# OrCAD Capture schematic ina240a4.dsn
size A; title: INA293 40-V High-Voltage, High Bandwidth, Unidirectional, 110-V Common-Mode Current-Sense Amplifier; rev: A; note: SBOS870
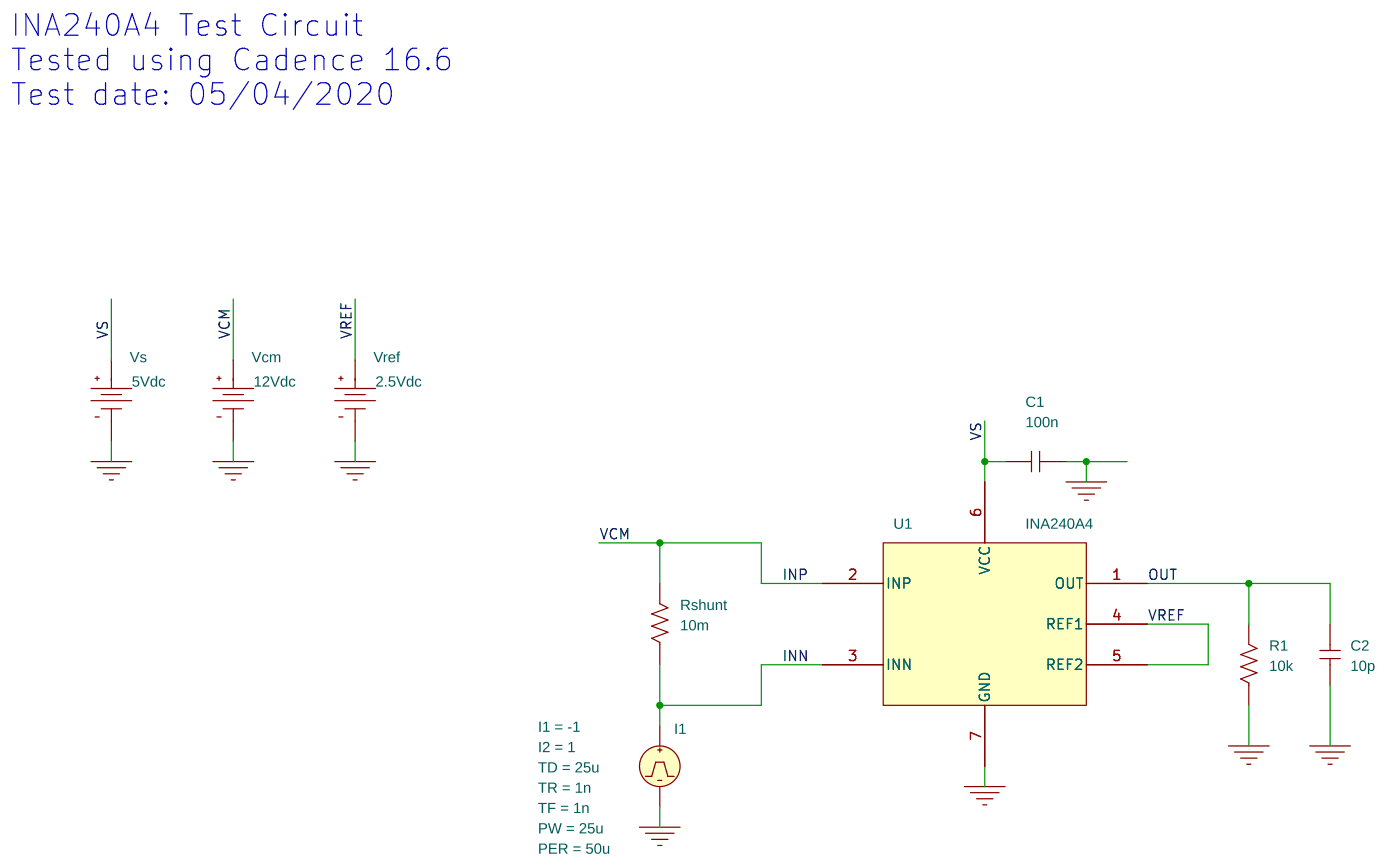
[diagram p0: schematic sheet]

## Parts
C1  100n  [RAD/CK05]
C2  10p  [RAD/CK05]
I1  IPULSE
R1  10k  [AX/RC05]
Rshunt  10m  [AX/RC05]
U1  INA240A4
Vcm  VDC
Vref  VDC
Vs  VDC

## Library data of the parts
C1 C2 = C
I1 = IPULSE: I1: -1; I2: 1; PER: 50u; PW: 25u; TD: 25u; TF: 1n; TR: 1n
R1 Rshunt = R
U1 = INA240A4
Vcm = VDC: DC: 12Vdc
Vref = VDC: DC: 2.5Vdc
Vs = VDC: DC: 5Vdc

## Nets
0: C1.1 C2.1 I1.2(-) R1.1 U1.7(GND) Vcm.1(-) Vref.1(-) Vs.1(-)
INN: I1.1(+) Rshunt.1 U1.3(INN)
INP: Rshunt.2 U1.2(INP) Vcm.0(+)
OUT: C2.2 R1.2 U1.1(OUT)
VREF: U1.4(REF1) U1.5(REF2) Vref.0(+)
VS: C1.2 U1.6(VCC) Vs.0(+)

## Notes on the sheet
- INA240A4 Test Circuit
  Tested using Cadence 16.6
  Test date: 05/04/2020
